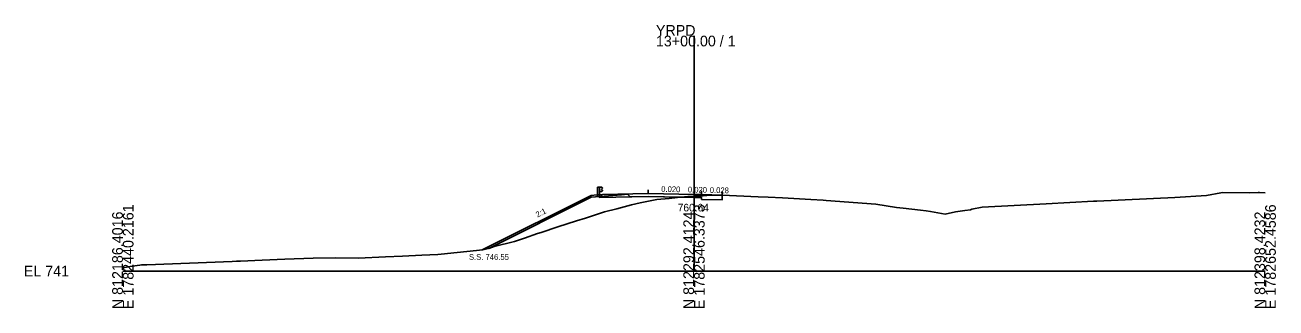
# Model space of a CAD drawing. Extents: x -26 to 1403, y -10 to 9544.
# Drawn here: x -25.7 to 302.8, y 2990.3 to 3064.5 of the extents above; entities that cross this region are included whole.
import ezdxf

# ---------------------------------------------------------------- set-up
doc = ezdxf.new("R2010")
doc.units = 0
for name, color, linetype in [('Exist Cross Section Cell', 7, 'Continuous'), ('Exist XS Center Line Elevation Label', 7, 'Continuous'), ('Exist XS Ground Line', 7, 'Continuous'), ('Prop XS Dump Level', 7, 'Continuous'), ('Prop XS Earthwork Shape', 7, 'Continuous'), ('Prop XS EOT Tick Mark', 7, 'Continuous'), ('Prop XS Finish Grade', 7, 'Continuous'), ('Prop XS Finish Grade Earthwork', 7, 'Continuous'), ('Prop XS Finish Grade Paved Shoulder', 7, 'Continuous'), ('Prop XS Finish Grade Pavement', 7, 'Continuous'), ('Prop XS Guardrail', 7, 'Continuous'), ('Prop XS Pvmt Edge Slope', 7, 'Continuous'), ('Prop XS SE Text', 7, 'Continuous'), ('Prop XS Side Slope Text', 7, 'Continuous'), ('Prop XS SS Elevation Text', 7, 'Continuous'), ('Prop XS Subgrade Earthwork', 7, 'Continuous')]:
    doc.layers.add(name, color=color, linetype=linetype)

msp = doc.modelspace()

# ---------------------------------------------------------------- linework, layer by layer
at = {"layer": 'Exist Cross Section Cell'}
for p, q in [((150, 3000), (150, 3061.75)), ((0, 3000), (150, 3000)), ((150, 3000), (300, 3000))]:
    msp.add_line(p, q, dxfattribs=at)
at = {"layer": 'Exist XS Ground Line'}
for p, q in [((143.5, 3019.06), (145.63, 3019.28)), ((145.63, 3019.28), (148.37, 3019.55)), ((148.37, 3019.55), (150, 3019.64)), ((150, 3019.64), (152.43, 3019.76)), ((152.43, 3019.76), (153.34, 3019.81)), ((153.34, 3019.81), (157.38, 3019.91)), ((157.38, 3019.91), (166.82, 3019.5)), ((166.82, 3019.5), (169.47, 3019.39)), ((169.47, 3019.39), (173.28, 3019.18)), ((255.78, 3018.31), (276.24, 3019.32)), ((276.24, 3019.32), (284.57, 3019.8)), ((284.57, 3019.8), (288.4, 3020.52)), ((288.4, 3020.52), (288.75, 3020.57)), ((288.75, 3020.57), (296.01, 3020.53)), ((296.01, 3020.53), (298.18, 3020.57)), ((298.18, 3020.57), (298.51, 3020.57)), ((298.51, 3020.57), (300, 3020.5)), ((126.53, 3015.54), (129.71, 3016.28)), ((129.71, 3016.28), (133.56, 3017.37)), ((133.56, 3017.37), (135.88, 3017.92)), ((135.88, 3017.92), (140.24, 3018.78)), ((140.24, 3018.78), (143.5, 3019.06)), ((173.28, 3019.18), (180.71, 3018.77)), ((180.71, 3018.77), (183.91, 3018.57)), ((183.91, 3018.57), (184.7, 3018.52)), ((184.7, 3018.52), (197.76, 3017.52)), ((197.76, 3017.52), (203.17, 3016.69)), ((203.17, 3016.69), (204.96, 3016.49)), ((204.96, 3016.49), (209.48, 3016.01)), ((209.48, 3016.01), (211.01, 3015.81)), ((221.12, 3015.91), (222.65, 3016.03)), ((222.65, 3016.03), (222.95, 3016.21)), ((222.95, 3016.21), (225.7, 3016.76)), ((225.7, 3016.76), (242.49, 3017.65)), ((242.49, 3017.65), (254.88, 3018.29)), ((254.88, 3018.29), (255.78, 3018.31)), ((114.23, 3011.56), (119.12, 3013.17)), ((119.12, 3013.17), (121.46, 3013.89)), ((121.46, 3013.89), (126.53, 3015.54)), ((211.01, 3015.81), (212.11, 3015.6)), ((212.11, 3015.6), (215.98, 3014.95)), ((215.98, 3014.95), (218.64, 3015.51)), ((218.64, 3015.51), (221.12, 3015.91)), ((105.48, 3008.65), (108.94, 3009.87)), ((108.94, 3009.87), (109.87, 3010.13)), ((109.87, 3010.13), (114.23, 3011.56)), ((95.95, 3005.88), (97.52, 3006.41)), ((97.52, 3006.41), (102.87, 3007.79)), ((102.87, 3007.79), (105.48, 3008.65)), ((30.9, 3002.62), (36.55, 3002.89)), ((36.55, 3002.89), (42.53, 3003.12)), ((42.53, 3003.12), (49.99, 3003.34)), ((49.99, 3003.34), (55.74, 3003.43)), ((55.74, 3003.43), (61.93, 3003.36)), ((61.93, 3003.36), (68.97, 3003.69)), ((68.97, 3003.69), (73.41, 3003.89)), ((73.41, 3003.89), (78.56, 3004.14)), ((78.56, 3004.14), (82.76, 3004.35)), ((82.76, 3004.35), (83.63, 3004.42)), ((83.63, 3004.42), (94.57, 3005.57)), ((94.57, 3005.57), (95.95, 3005.88)), ((0, 3000.88), (2.46, 3001.26)), ((2.46, 3001.26), (4.46, 3001.53)), ((4.46, 3001.53), (4.88, 3001.6)), ((4.88, 3001.6), (6.33, 3001.66)), ((6.33, 3001.66), (28.74, 3002.54)), ((28.74, 3002.54), (29.88, 3002.56)), ((29.88, 3002.56), (30.9, 3002.62))]:
    msp.add_line(p, q, dxfattribs=at)
at = {"layer": 'Prop XS Dump Level'}
for p, q in [((138, 3020.34), (150, 3020.1)), ((150, 3020.1), (152, 3020.06))]:
    msp.add_line(p, q, dxfattribs=at)
at = {"layer": 'Prop XS Earthwork Shape'}
for points in [[(96.1, 3005.93), (97.52, 3006.41), (102.87, 3007.79), (105.48, 3008.65), (108.94, 3009.87), (109.87, 3010.13), (114.23, 3011.56), (119.12, 3013.17), (121.46, 3013.89), (126.53, 3015.54), (129.71, 3016.28), (133.56, 3017.37), (135.88, 3017.92), (140.24, 3018.78), (143.5, 3019.06), (145.63, 3019.28), (146.6, 3019.38), (138, 3019.55), (133.19, 3019.45), (132.5, 3020.14), (131, 3020.02), (123, 3019.38)], [(146.6, 3019.38), (149.98, 3019.31), (152, 3019.27), (152, 3018.81), (157.38, 3018.66), (157.38, 3019.91), (153.34, 3019.81), (152.43, 3019.76), (150, 3019.64), (148.37, 3019.55)]]:
    msp.add_lwpolyline(points, close=True, dxfattribs=at)
at = {"layer": 'Prop XS EOT Tick Mark'}
for p, q in [((138, 3020.34), (138, 3021.34)), ((152, 3020.06), (152, 3021.06)), ((157.38, 3019.91), (157.38, 3020.91))]:
    msp.add_line(p, q, dxfattribs=at)
at = {"layer": 'Prop XS Finish Grade'}
msp.add_line((126, 3020.1), (124.5, 3019.98), dxfattribs=at)
at = {"layer": 'Prop XS Finish Grade Earthwork'}
for q in [(94.39, 3005.55), (124.5, 3019.98)]:
    msp.add_line((123, 3019.86), q, dxfattribs=at)
at = {"layer": 'Prop XS Finish Grade Paved Shoulder'}
for p, q in [((138, 3020.34), (126, 3020.1)), ((152, 3020.06), (157.38, 3019.91))]:
    msp.add_line(p, q, dxfattribs=at)
at = {"layer": 'Prop XS Finish Grade Pavement'}
for p, q in [((138, 3020.34), (150, 3020.1)), ((150, 3020.1), (152, 3020.06))]:
    msp.add_line(p, q, dxfattribs=at)
at = {"layer": 'Prop XS Guardrail'}
for p, q in [((124.68, 3022.02), (125.18, 3022.02)), ((124.68, 3019.52), (124.68, 3022.02)), ((125.18, 3022.02), (125.68, 3022.02)), ((125.18, 3022.02), (125.18, 3019.52)), ((125.68, 3020.88), (125.18, 3020.88)), ((125.68, 3022.02), (125.97, 3021.82)), ((125.97, 3021.7), (125.68, 3021.5)), ((125.68, 3021.5), (125.68, 3021.4)), ((125.68, 3021.4), (125.97, 3021.2)), ((125.97, 3021.08), (125.68, 3020.88)), ((125.97, 3021.82), (126, 3021.76)), ((126, 3021.76), (125.97, 3021.7)), ((125.97, 3021.2), (126, 3021.14)), ((126, 3021.14), (125.97, 3021.08))]:
    msp.add_line(p, q, dxfattribs=at)
at = {"layer": 'Prop XS Pvmt Edge Slope'}
msp.add_line((126, 3020.1), (125.19, 3019.29), dxfattribs=at)
at = {"layer": 'Prop XS Subgrade Earthwork'}
for p, q in [((125.19, 3019.29), (124.5, 3019.98)), ((138, 3019.55), (125.19, 3019.29)), ((138, 3019.55), (149.98, 3019.31)), ((149.98, 3019.31), (152, 3019.27)), ((152, 3018.81), (152, 3019.27)), ((157.38, 3018.66), (157.38, 3019.91)), ((152, 3018.81), (157.38, 3018.66))]:
    msp.add_line(p, q, dxfattribs=at)

# ---------------------------------------------------------------- texts
at = {"layer": 'Exist Cross Section Cell'}
for s, p in [('YRPD', (140, 3061.75)), ('13+00.00 / 1', (140, 3058.95)), ('EL 741', (-26, 2998.6))]:
    msp.add_text(s, height=2.8, dxfattribs=at).set_placement(p)
for s, p in [('E 1782440.2161', (2.8, 2990)), ('E 1782546.3373', (152.8, 2990)), ('E 1782652.4586', (302.8, 2990)), ('N 812186.4016', (0, 2990)), ('N 812292.4124', (150, 2990)), ('N 812398.4232', (300, 2990))]:
    msp.add_text(s, height=2.8, rotation=90, dxfattribs=at).set_placement(p)
at = {"layer": 'Exist XS Center Line Elevation Label'}
msp.add_text('760.64', height=2, dxfattribs=at).set_placement((145.72, 3015.64))
at = {"layer": 'Prop XS Dump Level'}
msp.add_text('Case4', height=0.04, dxfattribs=at).set_placement((126, 3019.58))
at = {"layer": 'Prop XS SE Text'}
for s, p in [('0.020', (141.38, 3020.77)), ('0.020', (148.38, 3020.63)), ('0.028', (154.13, 3020.5))]:
    msp.add_text(s, height=1.5, rotation=358.8542, dxfattribs=at).set_placement(p)
at = {"layer": 'Prop XS Side Slope Text'}
msp.add_text('2:1', height=1.5, rotation=26.5651, dxfattribs=at).set_placement((108.88, 3014))
at = {"layer": 'Prop XS SS Elevation Text'}
msp.add_text('S.S. 746.55', height=1.5, dxfattribs=at).set_placement((90.9, 3002.93))

doc.saveas('drawing.dxf')
